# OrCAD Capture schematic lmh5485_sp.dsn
size A
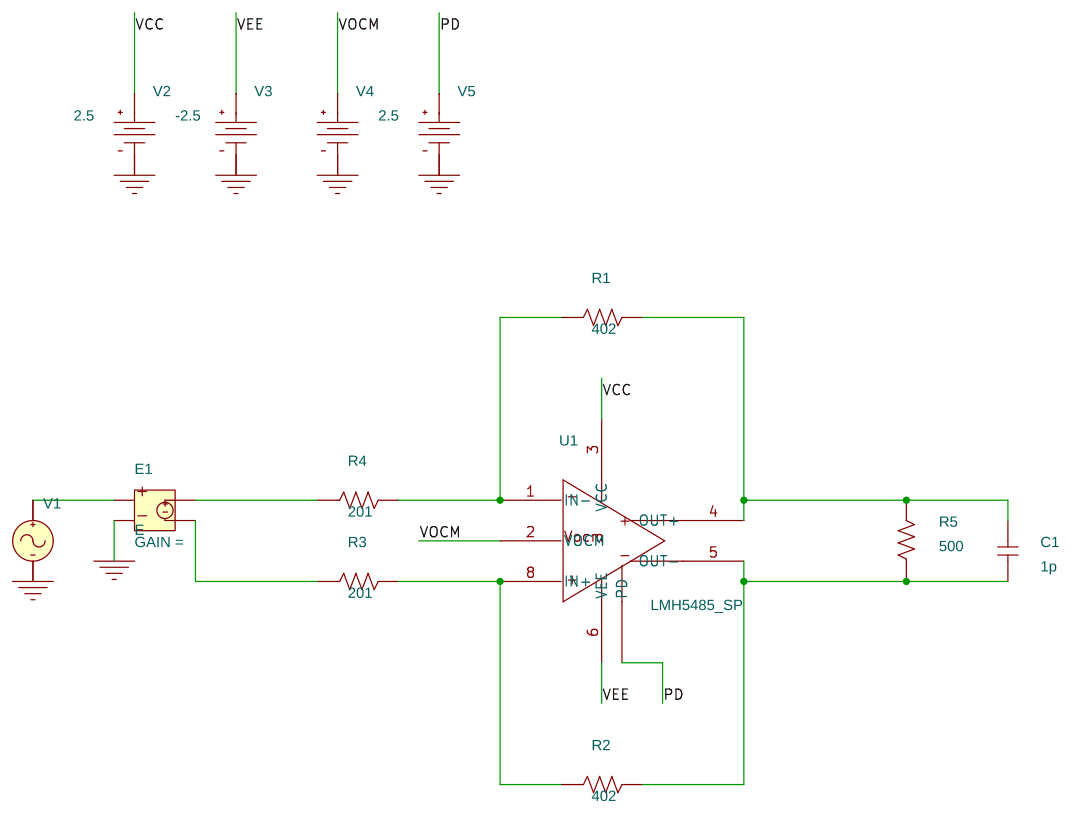
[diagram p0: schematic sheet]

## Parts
C1  1p  [cap196]
E1  E
R1  402  [AXRC05]
R2  402  [AXRC05]
R3  201  [AXRC05]
R4  201  [AXRC05]
R5  500  [AXRC05]
U1  LMH5485_SP
V1  VAC
V2  VDC
V3  VDC
V4  VDC
V5  VDC

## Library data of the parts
C1 = C
E1 = E
R1-R5 = R
U1 = LMH5485_SP
V1 = VAC
V2 V5 = VDC: DC: 2.5
V3 = VDC: DC: -2.5
V4 = VDC

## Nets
VCC: U1.3(VCC) V2.0(+)
VEE: U1.6(VEE) V3.0(+)
0: E1.2 V1.2(-) V2.1(-) V3.1(-) V4.1(-) V5.1(-)
PD: U1.PD V5.0(+)
VOCM: U1.2(VOCM) V4.0(+)
N00207: C1.1 R2.2 R5.1 U1.5(OUT-)
N00214: C1.2 R1.2 R5.2 U1.4(OUT+)
N00221: R1.1 R4.2 U1.1(IN-)
N00228: R2.1 R3.2 U1.8(IN+)
N00341: E1.4 R3.1
N01203: E1.1 V1.1(+)
N01239: E1.3 R4.1
